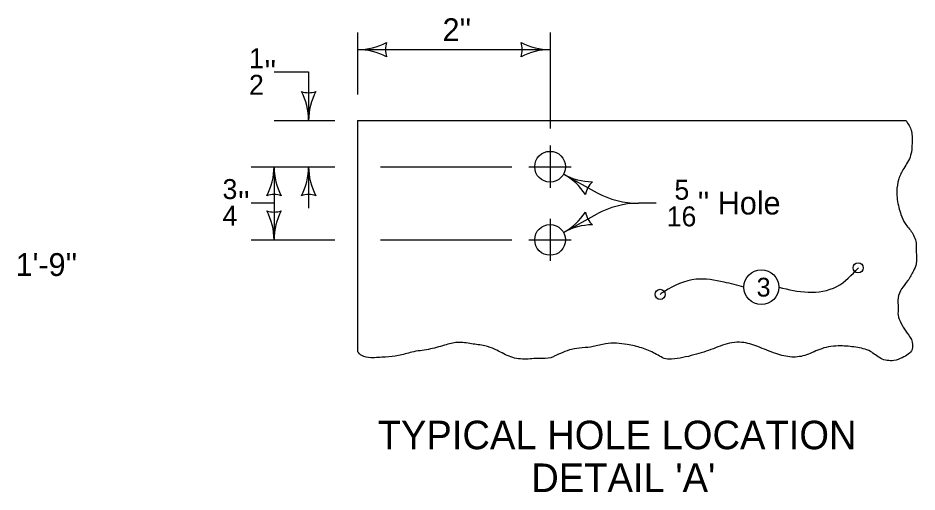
# Model space of a CAD drawing. Extents: x 228 to 3572, y -1307 to 1277.
# Drawn here: x 1692 to 2323, y -471 to -139 of the extents above; entities that cross this region are included whole.
import ezdxf

# ---------------------------------------------------------------- set-up
doc = ezdxf.new("R2010")
doc.units = 0
for name, color, linetype in [('dsnStdDimension', 7, 'Continuous'), ('Level 2', 7, 'Continuous'), ('Level 3', 7, 'Continuous')]:
    doc.layers.add(name, color=color, linetype=linetype)

msp = doc.modelspace()

# ---------------------------------------------------------------- linework, layer by layer
at = {"layer": 'dsnStdDimension'}
for p, q in [((1930.31, -149.05), (1930.31, -192.62)), ((2065.31, -149.05), (2065.31, -216.39)), ((1930.31, -161.05), (2065.31, -161.05)), ((1871.71, -176.58), (1895.95, -176.58)), ((1895.95, -176.58), (1895.95, -210.79)), ((1871.71, -210.79), (1914.31, -210.79)), ((1855.71, -243.19), (1914.31, -243.19)), ((1871.71, -243.19), (1871.71, -294.49)), ((1895.95, -243.19), (1895.95, -272.13)), ((1946.31, -243.19), (2038.51, -243.19)), ((2074.77, -248.4), (2098.29, -261.38)), ((1871.71, -268.84), (1855.71, -268.84)), ((2139.77, -268.84), (2127.26, -268.84)), ((2074.77, -289.27), (2098.29, -276.3)), ((1855.71, -294.49), (1914.31, -294.49)), ((1946.31, -294.49), (2038.51, -294.49))]:
    msp.add_line(p, q, dxfattribs=at)
for centre in [(2281.44, -314.11), (2142.49, -332.68)]:
    msp.add_circle(centre, 3.56, dxfattribs=at)
for centre, radius, start, end in [((1930.31, -117.87), 43.18, 270, 298.07249), ((1966.52, -161.05), 16.68, 162.26665, 197.73335), ((2029.1, -161.05), 16.68, 342.26665, 17.73335), ((2065.31, -117.87), 43.18, 241.92751, 270), ((1930.31, -204.23), 43.18, 61.92751, 90), ((2065.31, -204.23), 43.18, 90, 118.07249), ((1895.95, -174.58), 16.68, 252.26665, 287.73335), ((1852.77, -210.79), 43.18, 0, 28.07249), ((1939.13, -210.79), 43.18, 151.92751, 180), ((1828.53, -243.19), 43.18, 331.92751, 0), ((1914.89, -243.19), 43.18, 180, 208.07249), ((1852.77, -243.19), 43.18, 331.92751, 0), ((1939.13, -243.19), 43.18, 180, 208.07249), ((2053.91, -286.21), 43.18, 33.04402, 61.11651), ((2095.62, -210.59), 43.18, 241.11651, 269.189), ((2106.47, -265.89), 16.68, 133.38316, 168.84986), ((1871.71, -279.39), 16.68, 72.26665, 107.73335), ((1895.95, -279.39), 16.68, 72.26665, 107.73335), ((2127.26, -208.84), 60, 241.12699, 270), ((2127.26, -328.84), 60, 90, 118.87716), ((1871.71, -258.28), 16.68, 252.26665, 287.73335), ((1828.53, -294.49), 43.18, 0, 28.07249), ((1914.89, -294.49), 43.18, 151.92751, 180), ((2053.91, -251.46), 43.18, 298.88182, 326.95431), ((2106.47, -271.78), 16.68, 191.14847, 226.61517), ((2095.62, -327.08), 43.18, 90.80933, 118.88182)]:
    msp.add_arc(centre, radius, start, end, dxfattribs=at)
for points in [[(2225.77, -327.64), (2246.27, -331.17), (2266.42, -327.14), (2281.53, -314.03)], [(2201.27, -327.64), (2187.32, -324.11), (2167.68, -322.1), (2145.51, -330.67), (2142.49, -332.68)]]:
    msp.add_spline(points, degree=3, dxfattribs=at)
at = {"layer": 'Level 2'}
for p, q in [((1930.31, -210.79), (2314.93, -210.79)), ((1930.31, -210.79), (1930.31, -372.76)), ((2065.31, -228.39), (2065.31, -257.98)), ((2050.51, -243.19), (2080.11, -243.19)), ((2065.31, -279.69), (2065.31, -309.28)), ((2050.51, -294.49), (2080.11, -294.49))]:
    msp.add_line(p, q, dxfattribs=at)
for centre, radius in [((2065.31, -243.19), 10.8), ((2065.31, -294.49), 10.8), ((2213.52, -327.64), 12.25)]:
    msp.add_circle(centre, radius, dxfattribs=at)
msp.add_spline([(2314.93, -210.79), (2318.68, -218.12), (2319.17, -226.41), (2318.2, -235.19), (2313.32, -244.45), (2309.91, -251.77), (2308.45, -260.55), (2309.91, -271.76), (2311.37, -276.64), (2314.3, -282.98), (2319.17, -289.32), (2322.09, -297.61), (2322.09, -302.98), (2322.09, -311.27), (2320.15, -316.14), (2316.25, -322.97), (2311.86, -328.82), (2309.42, -335.17), (2309.42, -341.99), (2309.42, -347.36), (2311.37, -352.72), (2314.78, -358.57), (2318.68, -364.43), (2319.17, -371.26), (2312.35, -377.11), (2306.5, -379.06), (2297.24, -377.59), (2289.93, -372.72), (2279.7, -369.79), (2268.98, -368.82), (2255.82, -370.77), (2245.1, -375.16), (2234.87, -376.62), (2223.66, -374.18), (2210.99, -369.31), (2199.78, -366.38), (2186.14, -368.33), (2179.8, -370.77), (2166.16, -375.16), (2150.56, -378.08), (2147.64, -378.08), (2138.87, -374.18), (2129.61, -370.28), (2119.38, -367.84), (2104.27, -367.35), (2095.5, -369.31), (2080.39, -371.26), (2068.21, -376.13), (2065.77, -377.11), (2057.98, -377.59), (2047.26, -378.08), (2036.53, -376.13), (2026.79, -371.26), (2019.48, -368.82), (2010.22, -367.35), (2000.47, -366.38), (1991.22, -368.33), (1980.01, -371.26), (1968.31, -373.21), (1959.05, -375.64), (1949.8, -376.62), (1939.56, -377.11), (1933.23, -375.64), (1930.31, -372.76)], degree=3, dxfattribs=at)

# ---------------------------------------------------------------- texts
at = {"layer": 'dsnStdDimension'}
for s, height, p in [("2''", 16, (1989.89, -155.12)), ('1', 14, (1854.14, -174.09)), ("'' ", 16, (1865.01, -184.42)), ('2', 14, (1854.14, -192.75)), ('3', 14, (1835.56, -265.85)), ('5', 14, (2152.51, -266.33)), ("'' ", 16, (1846.43, -276.18)), ("'' Hole", 16, (2168.82, -276.66)), ('4', 14, (1835.56, -284.51)), ('16', 14, (2147.07, -285)), ("1'-9''", 16, (1690.47, -319.78))]:
    msp.add_text(s, height=height, dxfattribs=at).set_placement(p)
at = {"layer": 'Level 2'}
msp.add_text('3', height=13.2, dxfattribs=at).set_placement((2210.12, -334.24))
at = {"layer": 'Level 3'}
for s, p in [('TYPICAL HOLE LOCATION', (1944.37, -441.28)), ("DETAIL 'A'", (2052.1, -471.28))]:
    msp.add_text(s, height=20, dxfattribs=at).set_placement(p)

doc.saveas('drawing.dxf')
